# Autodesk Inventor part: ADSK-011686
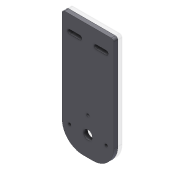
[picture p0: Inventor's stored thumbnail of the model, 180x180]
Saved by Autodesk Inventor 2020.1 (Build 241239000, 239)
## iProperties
Created: 2000-02
Part Number: ADSK-011686
Material: Pearson HRS
Description: PLT-24,FH,CP,03,050,115,MNT,BEARING
Document SubType Name: Modeling
Designer: sspink
Density: 7.83 g/cm^3
Appearance: Métal - Acier
Mass: 2746.38 g
Surface Area: 810.24 cm^2
Volume: 350.751 cm^3
Control State: 0
Master: False
Checked Out: False
Shininess: 0.0
Length Units: 11269
Angle Units: 11279
Time Units: 11290
Mass Units: 11283
Length Display Precision: 3
Angle Display Precision: 2
Compacted: True
Cutlength: 11.5
Material Desc: FLAT,HRS,0.38 X 5.00
Material_Number: A084412
Dimensions: 127x294x10 mm
Mass: 2,746 kg
DocNumber: ADSK-011686.ipt
Folder: 01 - Themengebiete\Simplification\01 - Packaging machine\
VDS_Category: 3D Komponenten
Density: 0.0
Volumn: 0.0
Area: 0.0
PropertySet Name: Model Information
Author: sspink
Revision Number: -
Title: fixing plate
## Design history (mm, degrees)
node "Solide1"
  node "Extrusion1" dims "d2" = 10, "d3" = 0
  node "Hole1" dims "d5" = 22, "d6" = 9.525, "d7" = 6.35, "d8" = 60 deg, "d9" = 19.05, "d10" = 118 deg, "d38" = 6
  node "Fillet1" dims "d11" = 50.8
  node "Extrusion2" dims "d17" = 9.525, "d18" = 0
  node "Fillet2" dims "d19" = 6
  node "Hole2" dims "d22" = 6.5, "d23" = 9.525, "d24" = 6.35, "d25" = 60 deg, "d26" = 19.05, "d27" = 118 deg, "d45" = 6
  node "Hole3" dims "d32" = 6.647, "d33" = 9.525, "d34" = 6.35, "d35" = 60 deg, "d36" = 19.05, "d37" = 118 deg, "d47" = 16
sketch "Sketch1"
  geometry: L1 (-63.5, -147)-(63.5, -147); L2 (63.5, -147)-(63.5, 147); L3 (63.5, 147)-(-63.5, 147); L4 (-63.5, 147)-(-63.5, -147); 3 further points
  constraints: 8 end point, 2 midpoint, 2 parallel, 1 horizontal, 1 horizontal alignment, 1 perpendicular, 1 vertical alignment
  dimensions: "d0" = 127 distance between parallel lines of L2 L4; "d1" = 294 distance between parallel lines of L1 L3
sketch "Sketch2"
  geometry: L1 (63.5, -147)-(-63.5, -147) reference; L2 (-63.5, 147)-(63.5, 147) reference; L3 (0, 147)-(0, -147); 1 further point
  constraints: 2 end point, 2 midpoint, 1 point on line
  dimensions: "d4" = 49 distance from line of point (0, -98) L1
sketch "Sketch3"
  geometry: L1 (-63.5, 147)-(63.5, 147) reference; L2 (20, 109.5)-(45, 109.5); L3 (20, 104.5)-(45, 104.5); L4 (45, 114.5)-(20, 114.5); L5 (-45, 109.5)-(-20, 109.5); L6 (-45, 104.5)-(-20, 104.5); L7 (-20, 114.5)-(-45, 114.5); L8 (-32.5, 109.5)-(32.5, 109.5); A1 r 5 centre (20, 109.5) between (20, 114.5) and (20, 104.5); A2 r 5 centre (45, 109.5) between (45, 104.5) and (45, 114.5); A3 r 5 centre (-20, 109.5) between (-20, 104.5) and (-20, 114.5); A4 r 5 centre (-45, 109.5) between (-45, 114.5) and (-45, 104.5); 2 further points
  constraints: 18 end point, 8 point on circle, 8 tangent, 4 centre point, 4 midpoint, 3 horizontal, 2 parallel, 1 collinear, 1 vertical alignment
  dimensions: "d39" = 25 distance of L2.start L2.end; "d40" = 10 distance between parallel lines of L4 L3; "d41" = 25 distance of L5.start L5.end; "d42" = 10 distance between parallel lines of L7 L6; "d43" = 65 distance of L8.end L8.start; "d44" = 37.5 distance between parallel lines of L1 L5
sketch "Sketch4"
  geometry: C1 r 3.175 at (0, -56); C2 r 11 at (0, -98) reference; 1 further point
  constraints: 1 centre point, 1 coincident, 1 vertical alignment
  dimensions: "d48" = 42 distance of C2.centre point (0, -56)
sketch "Sketch5"
  geometry: L1 (-57.5, 147)-(57.5, 147) reference; L2 (12.7, -147)-(-12.7, -147) reference; L3 (0, 147)-(0, -147); L4 (-45, -98)-(45, -98); C1 r 11 at (0, -98) reference; 1 further point
  constraints: 4 end point, 4 midpoint, 1 horizontal, 1 point on line
  dimensions: "d46" = 90 distance of L4.start L4.end
node "Corps solides"
node "Corps surfaciques"
